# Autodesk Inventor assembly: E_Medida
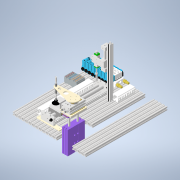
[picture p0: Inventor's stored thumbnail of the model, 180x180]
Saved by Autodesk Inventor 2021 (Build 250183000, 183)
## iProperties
Created: 2021-02
Part Number: E_Medida
Document SubType Name: Assembly
Designer: ATOUZA
Author: ATOUZA
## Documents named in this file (21)
- D:\01 Paralaia\Grupos de Traballo\GT Maquetas\CAD 3D\E_Medida\E_Medida.iam
- D:\01 Paralaia\Grupos de Traballo\GT Maquetas\CAD 3D\E_Medida\CY1S15-250\CY1S15-250Z-M9B(0_0_0).iam
- D:\01 Paralaia\Grupos de Traballo\GT Maquetas\CAD 3D\E_Medida\SMC_JP_MSQXB10AM9B0\MSQXB10A-M9B(0).iam
- D:\01 Paralaia\Grupos de Traballo\GT Maquetas\CAD 3D\E_Medida\Perfil 20x20 B R6.ipt
- D:\01 Paralaia\Grupos de Traballo\GT Maquetas\CAD 3D\E_Medida\CilindroElevador\CilindroElevador.iam
- D:\01 Paralaia\Grupos de Traballo\GT Maquetas\CAD 3D\E_Medida\Perfil 20x20 B R6-Corto.ipt
- D:\01 Paralaia\Grupos de Traballo\GT Maquetas\CAD 3D\E_Medida\Placa cilindro rotatorio.ipt
- D:\01 Paralaia\Grupos de Traballo\GT Maquetas\CAD 3D\E_Medida\Placa cilindro elevador.ipt
- D:\01 Paralaia\Grupos de Traballo\GT Maquetas\CAD 3D\E_Medida\Brazo cilindro rotatorio.ipt
- D:\01 Paralaia\Grupos de Traballo\GT Maquetas\CAD 3D\E_Medida\ZPT32SCK30\ZPT32CSK30-04-A10_(S) Silicon rubber.iam
- D:\01 Paralaia\Grupos de Traballo\GT Maquetas\CAD 3D\E_Medida\CY3R10-50-M9B\CY3R10-50-M9B(0_0_0).iam
- D:\01 Paralaia\Grupos de Traballo\GT Maquetas\CAD 3D\E_Medida\PlacaBaseDeslizador.ipt
- D:\01 Paralaia\Grupos de Traballo\GT Maquetas\CAD 3D\E_Medida\Perfil 20x20 B R6 Columna.ipt
- D:\01 Paralaia\Grupos de Traballo\GT Maquetas\CAD 3D\E_Medida\ResistenciaKTR\Resistencia KTR.iam
- D:\01 Paralaia\Grupos de Traballo\GT Maquetas\CAD 3D\E_Medida\Cubo.ipt
- D:\01 Paralaia\Grupos de Traballo\GT Maquetas\CAD 3D\E_Medida\PlacaUnionKTR.ipt
- D:\01 Paralaia\Grupos de Traballo\GT Maquetas\CAD 3D\E_Medida\BasePieza.ipt
- D:\01 Paralaia\Grupos de Traballo\GT Maquetas\CAD 3D\E_Medida\BasePiezaPosición.ipt
- D:\01 Paralaia\Grupos de Traballo\GT Maquetas\CAD 3D\E_Medida\Electroválvulas\BloqueElectroválvulas.iam
- D:\01 Paralaia\Grupos de Traballo\GT Maquetas\CAD 3D\E_Medida\Borne para detectoresactuadores - PTIO 1,5-S-3 - 3244410\pxc_3244410_02_PTIO-1-5-S-3_3D.ipt
- D:\01 Paralaia\Grupos de Traballo\GT Maquetas\CAD 3D\E_Medida\Canaleta 30x30\7308-1.iam
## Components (54 placed, 19 different names)
1. CY1S15-250Z-M9B(0_0_0):1 [sub-assembly] — Coincidencia:1, Ángulo:1, Coincidencia:7, Nivelación:10, Insertar:8, Insertar:9, Insertar:10, Insertar:11, Nivelación:12, Coincidencia:9, Nivelación:14, Insertar:14, Insertar:15
2. MSQXB10A-M9B(0):1 [sub-assembly] — Ángulo:3, Insertar:1, Insertar:2, Nivelación:9, Coincidencia:6, Ángulo:4, Coincidencia:7
3. CilindroElevador:1 [sub-assembly] — Ángulo:2, Coincidencia:3, Nivelación:2, Nivelación:4, Insertar:6, Nivelación:8
4. Placa cilindro rotatorio:1 — Insertar:1, Insertar:2, Insertar:3, Insertar:5
5. Placa cilindro elevador:1 — Insertar:3, Insertar:5, Insertar:6, Nivelación:8
6. Brazo cilindro rotatorio:1 — Nivelación:9, Coincidencia:6, Ángulo:4, Insertar:7
7. ZPT32CSK30-04-A10_(S) Silicon rubber:1 [sub-assembly] — Insertar:7
8. CY3R10-50-M9B(0_0_0):1 [sub-assembly] — Nivelación:13, Coincidencia:11, Coincidencia:12, Insertar:12, Insertar:13
9. PlacaBaseDeslizador:1 — Insertar:8, Insertar:9
10. PlacaBaseDeslizador:2 — Insertar:10, Insertar:11
11. Perfil 20x20 B R6 480:21 — Coincidencia:8, Nivelación:11, Nivelación:12, Nivelación:13, Coincidencia:11
12. Resistencia KTR:1 [sub-assembly] — Nivelación:14, Coincidencia:13, Nivelación:15
13. Cubo:1 — Coincidencia:9, Coincidencia:14, Coincidencia:15, Coincidencia:16
14. PlacaUnionKTR:1 — Insertar:12, Insertar:13, Coincidencia:13, Nivelación:15
15. BasePieza:1 — Insertar:14, Insertar:15, Insertar:16, Insertar:17, Coincidencia:14
16. BasePiezaPosición:1 — Insertar:16, Insertar:17, Coincidencia:15, Coincidencia:16
17. BloqueElectroválvulas:1 [sub-assembly] — Coincidencia:17, Nivelación:21
18. 7308-1:3 [sub-assembly]
19. Perfil 20x20 B R6 480:1 — Nivelación:1, Coincidencia:3, Nivelación:2, Coincidencia:4, Nivelación:6, Nivelación:7, Coincidencia:5, Coincidencia:8, Nivelación:11
20. Perfil 20x20 B R6 480:2
21. Perfil 20x20 B R6 480:3 — Coincidencia:12
22. Perfil 20x20 B R6 480:4
23. Perfil 20x20 B R6 480:5
24. Perfil 20x20 B R6 480:6 — Nivelación:4, Nivelación:10
25. Perfil 20x20 B R6 480:7
26. Perfil 20x20 B R6 480:8 — Coincidencia:18
27. Perfil 20x20 B R6 480:9
28. Perfil 20x20 B R6 480:10 — Ángulo:1
29. Perfil 20x20 B R6 480:11 — Coincidencia:17
30. Perfil 20x20 B R6 480:12 — Nivelación:21
31. Perfil 20x20 B R6 480:13 — Coincidencia:19
32. Perfil 20x20 B R6 480:15
33. Perfil 20x20 B R6 480:16
34. Perfil 20x20 B R6 480:17 — Nivelación:6
35. Perfil 20x20 B R6 480:18 — Nivelación:5, Coincidencia:4
36. Perfil 20x20 B R6 480:19 — Coincidencia:5
37. Perfil 20x20 B R6 480:20 — Nivelación:7
38. pxc_3244410_02_PTIO-1-5-S-3_3D:2 — Coincidencia:19
39. pxc_3244410_02_PTIO-1-5-S-3_3D:3
40. pxc_3244410_02_PTIO-1-5-S-3_3D:4
41. pxc_3244410_02_PTIO-1-5-S-3_3D:5
42. pxc_3244410_02_PTIO-1-5-S-3_3D:6
43. pxc_3244410_02_PTIO-1-5-S-3_3D:7
44. pxc_3244410_02_PTIO-1-5-S-3_3D:8
45. pxc_3244410_02_PTIO-1-5-S-3_3D:9
46. pxc_3244410_02_PTIO-1-5-S-3_3D:10
47. pxc_3244410_02_PTIO-1-5-S-3_3D:11
48. pxc_3244410_02_PTIO-1-5-S-3_3D:12
49. pxc_3244410_02_PTIO-1-5-S-3_3D:13
50. pxc_3244410_02_PTIO-1-5-S-3_3D:14
51. pxc_3244410_02_PTIO-1-5-S-3_3D:15
52. Canaleta [sub-assembly] — Coincidencia:18
53. 7308-1:2 [sub-assembly]
54. 7308-1:4 [sub-assembly]
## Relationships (52: Mate 17, Insert 16, Flush 15, Angle 4)
- Coincidencia:1 [Mate]: CY1S15-250Z-M9B(0_0_0):1
- Nivelación:1 [Flush]: Perfil 20x20 B R6 480:1
- Ángulo:1 [Angle]: CY1S15-250Z-M9B(0_0_0):1 ↔ Perfil 20x20 B R6 480:10
- Ángulo:2 [Angle]: CilindroElevador:1
- Coincidencia:3 [Mate]: CilindroElevador:1 ↔ Perfil 20x20 B R6 480:1
- Nivelación:2 [Flush]: CilindroElevador:1 ↔ Perfil 20x20 B R6 480:1
- Nivelación:4 [Flush]: CilindroElevador:1 ↔ Perfil 20x20 B R6 480:6
- Nivelación:5 [Flush]: Perfil 20x20 B R6 480:18
- Coincidencia:4 [Mate]: Perfil 20x20 B R6 480:1 ↔ Perfil 20x20 B R6 480:18
- Nivelación:6 [Flush]: Perfil 20x20 B R6 480:1 ↔ Perfil 20x20 B R6 480:17
- Nivelación:7 [Flush]: Perfil 20x20 B R6 480:1 ↔ Perfil 20x20 B R6 480:20
- Coincidencia:5 [Mate]: Perfil 20x20 B R6 480:1 ↔ Perfil 20x20 B R6 480:19
- Ángulo:3 [Angle]: MSQXB10A-M9B(0):1
- Insertar:1: MSQXB10A-M9B(0):1 ↔ Placa cilindro rotatorio:1
- Insertar:2: MSQXB10A-M9B(0):1 ↔ Placa cilindro rotatorio:1
- Insertar:3: Placa cilindro rotatorio:1 ↔ Placa cilindro elevador:1
- Insertar:5: Placa cilindro rotatorio:1 ↔ Placa cilindro elevador:1
- Insertar:6: CilindroElevador:1 ↔ Placa cilindro elevador:1
- Nivelación:8 [Flush]: CilindroElevador:1 ↔ Placa cilindro elevador:1
- Nivelación:9 [Flush]: MSQXB10A-M9B(0):1 ↔ Brazo cilindro rotatorio:1
- Coincidencia:6 [Mate]: MSQXB10A-M9B(0):1 ↔ Brazo cilindro rotatorio:1
- Ángulo:4 [Angle]: MSQXB10A-M9B(0):1 ↔ Brazo cilindro rotatorio:1
- Coincidencia:7 [Mate]: CY1S15-250Z-M9B(0_0_0):1 ↔ MSQXB10A-M9B(0):1
- Insertar:7: Brazo cilindro rotatorio:1 ↔ ZPT32CSK30-04-A10_(S) Silicon rubber:1
- Nivelación:10 [Flush]: CY1S15-250Z-M9B(0_0_0):1 ↔ Perfil 20x20 B R6 480:6
- Insertar:8: CY1S15-250Z-M9B(0_0_0):1 ↔ PlacaBaseDeslizador:1
- Insertar:9: CY1S15-250Z-M9B(0_0_0):1 ↔ PlacaBaseDeslizador:1
- Insertar:10: CY1S15-250Z-M9B(0_0_0):1 ↔ PlacaBaseDeslizador:2
- Insertar:11: CY1S15-250Z-M9B(0_0_0):1 ↔ PlacaBaseDeslizador:2
- Coincidencia:8 [Mate]: Perfil 20x20 B R6 480:21 ↔ Perfil 20x20 B R6 480:1
- Nivelación:11 [Flush]: Perfil 20x20 B R6 480:21 ↔ Perfil 20x20 B R6 480:1
- Nivelación:12 [Flush]: CY1S15-250Z-M9B(0_0_0):1 ↔ Perfil 20x20 B R6 480:21
- Nivelación:13 [Flush]: CY3R10-50-M9B(0_0_0):1 ↔ Perfil 20x20 B R6 480:21
- Coincidencia:9 [Mate]: CY1S15-250Z-M9B(0_0_0):1 ↔ Cubo:1
- Coincidencia:11 [Mate]: CY3R10-50-M9B(0_0_0):1 ↔ Perfil 20x20 B R6 480:21
- Nivelación:14 [Flush]: CY1S15-250Z-M9B(0_0_0):1 ↔ Resistencia KTR:1
- Coincidencia:12 [Mate]: CY3R10-50-M9B(0_0_0):1 ↔ Perfil 20x20 B R6 480:3
- Insertar:12: CY3R10-50-M9B(0_0_0):1 ↔ PlacaUnionKTR:1
- Insertar:13: CY3R10-50-M9B(0_0_0):1 ↔ PlacaUnionKTR:1
- Coincidencia:13 [Mate]: Resistencia KTR:1 ↔ PlacaUnionKTR:1
- Nivelación:15 [Flush]: Resistencia KTR:1 ↔ PlacaUnionKTR:1
- Insertar:14: CY1S15-250Z-M9B(0_0_0):1 ↔ BasePieza:1
- Insertar:15: CY1S15-250Z-M9B(0_0_0):1 ↔ BasePieza:1
- Insertar:16: BasePieza:1 ↔ BasePiezaPosición:1
- Insertar:17: BasePieza:1 ↔ BasePiezaPosición:1
- Coincidencia:14 [Mate]: Cubo:1 ↔ BasePieza:1
- Coincidencia:15 [Mate]: Cubo:1 ↔ BasePiezaPosición:1
- Coincidencia:16 [Mate]: Cubo:1 ↔ BasePiezaPosición:1
- Coincidencia:17 [Mate]: BloqueElectroválvulas:1 ↔ Perfil 20x20 B R6 480:11
- Coincidencia:18 [Mate]: Perfil 20x20 B R6 480:8 ↔ Canaleta
- Coincidencia:19 [Mate]: Perfil 20x20 B R6 480:13 ↔ pxc_3244410_02_PTIO-1-5-S-3_3D:2
- Nivelación:21 [Flush]: BloqueElectroválvulas:1 ↔ Perfil 20x20 B R6 480:12
